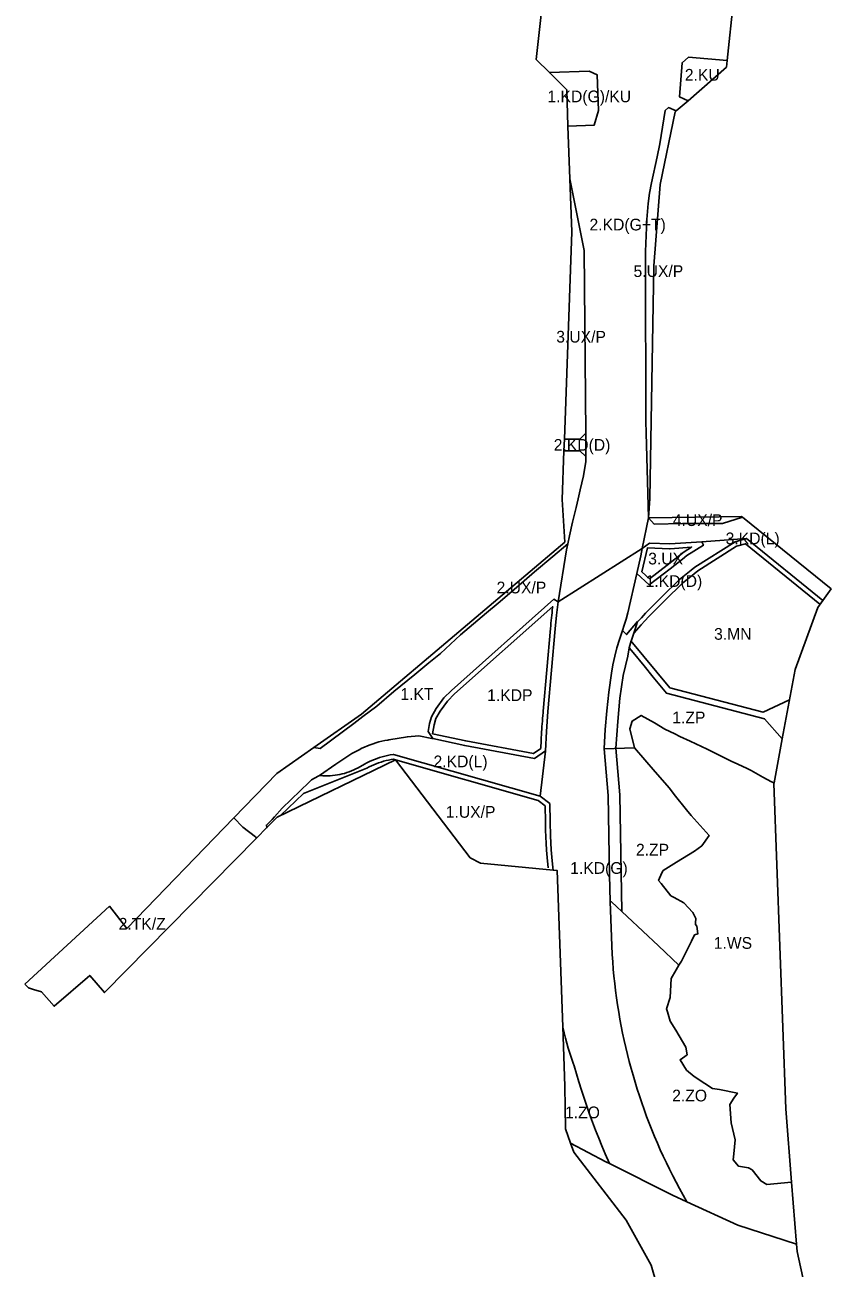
# Model space of a CAD drawing. Extents: x 7426363 to 7427567, y 5543397 to 5546605.
# Drawn here: x 7426639 to 7427327, y 5544381 to 5545441 of the extents above; entities that cross this region are included whole.
import ezdxf

# ---------------------------------------------------------------- set-up
doc = ezdxf.new("R2010")
doc.units = 0
for name, color, linetype in [('linie_rozgraniczajace', 7, 'Continuous'), ('linie_zabudowy_nieprzekraczalne', 7, 'Continuous'), ('oznaczenia_przeznaczen', 7, 'Continuous')]:
    doc.layers.add(name, color=color, linetype=linetype)

msp = doc.modelspace()

# ---------------------------------------------------------------- linework, layer by layer
at = {"layer": 'linie_rozgraniczajace'}
for points in [[(7427243.48, 5545461.46), (7427238, 5545410.26), (7427205.12, 5545413.11), (7427199.67, 5545408.45), (7427197.6, 5545379.31), (7427204.72, 5545376.04), (7427194.76, 5545367.3), (7427188.07, 5545370.22), (7427185.38, 5545367.62), (7427180.65, 5545339.35), (7427178.47, 5545328.2), (7427173.56, 5545306.18), (7427171.87, 5545297.31), (7427170.77, 5545288.36), (7427169.69, 5545274.8), (7427168.92, 5545261.23), (7427168.48, 5545247.63), (7427168.35, 5545234.03), (7427168.7, 5545106.16), (7427168.74, 5545102.69), (7427169.19, 5545093.12), (7427171, 5545020.58), (7427165.78, 5544994.33), (7427093.93, 5544948.99), (7427101.15, 5544993.39), (7427102.23, 5544998.52), (7427103.62, 5545005.17), (7427106.32, 5545016.91), (7427109.3, 5545029.28), (7427111.11, 5545036.83), (7427112.72, 5545044.43), (7427115.53, 5545056.38), (7427117.72, 5545068.46), (7427117.69, 5545072.74), (7427117.54, 5545092.74), (7427116.34, 5545248.29), (7427103.98, 5545309.55), (7427102.39, 5545354.39), (7427124.63, 5545355.18), (7427128.44, 5545367.58), (7427127.37, 5545397.96), (7427120.55, 5545401.26), (7427086.52, 5545400.06), (7427075.42, 5545411.1), (7427081.49, 5545467.8)], [(7427187.34, 5544335.36), (7427173.29, 5544383.64), (7427151.87, 5544421.91), (7427107.4, 5544479.92), (7427104.66, 5544487.48), (7427134.56, 5544471.82), (7427137.7, 5544470.25), (7427191.5, 5544443.31), (7427203.72, 5544437.69), (7427247.33, 5544417.64), (7427297.26, 5544401.56), (7427297.75, 5544395.41), (7427304.02, 5544366.49)]]:
    msp.add_lwpolyline(points, dxfattribs=at)
for points in [[(7427197.6, 5545379.31), (7427199.67, 5545408.45), (7427205.12, 5545413.11), (7427238, 5545410.26), (7427237.41, 5545404.75), (7427204.72, 5545376.04)], [(7427086.52, 5545400.06), (7427120.55, 5545401.26), (7427127.37, 5545397.96), (7427128.44, 5545367.58), (7427124.63, 5545355.18), (7427102.39, 5545354.39), (7427101.3, 5545385.36)], [(7427171, 5545020.58), (7427169.19, 5545093.12), (7427168.74, 5545102.69), (7427168.7, 5545106.16), (7427168.35, 5545234.03), (7427168.48, 5545247.63), (7427168.92, 5545261.23), (7427169.69, 5545274.8), (7427170.77, 5545288.36), (7427171.87, 5545297.31), (7427173.56, 5545306.18), (7427178.47, 5545328.2), (7427180.65, 5545339.35), (7427185.38, 5545367.62), (7427188.07, 5545370.22), (7427194.76, 5545367.3), (7427193.87, 5545366.52), (7427181.09, 5545304.56), (7427175.61, 5545235.36), (7427172.18, 5545037)], [(7427099.34, 5545087.55), (7427105.57, 5545264.4), (7427103.98, 5545309.55), (7427116.34, 5545248.29), (7427117.54, 5545092.74), (7427112.57, 5545087.69)], [(7427098.99, 5545077.54), (7427099.34, 5545087.55), (7427112.57, 5545087.69), (7427117.54, 5545092.74), (7427117.69, 5545072.74), (7427112.65, 5545077.69)], [(7426885.89, 5544824.84), (7426926.31, 5544853.27), (7427099.73, 5544999.86), (7427097.53, 5545036.19), (7427098.99, 5545077.54), (7427112.65, 5545077.69), (7427117.69, 5545072.74), (7427117.72, 5545068.46), (7427115.53, 5545056.38), (7427112.72, 5545044.43), (7427111.11, 5545036.83), (7427109.3, 5545029.28), (7427106.32, 5545016.91), (7427103.62, 5545005.17), (7427102.23, 5544998.52), (7427089.62, 5544987.72), (7427074, 5544974.42), (7427058.51, 5544961.08), (7427042.86, 5544947.85), (7427033.05, 5544939.55), (7427010.66, 5544920.74), (7426993.73, 5544905.07), (7426983.86, 5544896.95), (7426971.75, 5544887.07), (7426954.1, 5544872.43), (7426939.37, 5544859.96), (7426927.61, 5544851.14), (7426919.9, 5544845.35), (7426891.32, 5544823.92)], [(7427165.78, 5544994.33), (7427171, 5545020.58), (7427175.92, 5545015.09), (7427199.95, 5545015.84), (7427234.11, 5545015.81), (7427251.04, 5545021.15), (7427326.72, 5544960.01), (7427319.74, 5544950.23), (7427254.49, 5545002.94), (7427216.55, 5545000.22), (7427189.23, 5544998.26), (7427171.98, 5544998.98)], [(7427171, 5545020.58), (7427231.26, 5545021.26), (7427250.39, 5545021.68), (7427251.04, 5545021.15), (7427234.11, 5545015.81), (7427199.95, 5545015.84), (7427175.92, 5545015.09)], [(7427148.86, 5544924.57), (7427150.35, 5544928.96), (7427152, 5544934.25), (7427153.38, 5544939.62), (7427161.07, 5544973.02), (7427171.73, 5544963.47), (7427189.5, 5544977.01), (7427200.07, 5544985.43), (7427203.72, 5544988.33), (7427217.79, 5544997.2), (7427216.55, 5545000.22), (7427254.49, 5545002.94), (7427244.97, 5545000.17), (7427210.67, 5544978.53), (7427207.54, 5544976.04), (7427197.45, 5544968), (7427182.41, 5544953.33), (7427168.49, 5544939.21), (7427164.94, 5544935.46), (7427161.87, 5544932.17), (7427161.78, 5544932.06), (7427152.33, 5544921.06)], [(7427154.49, 5544909.73), (7427155.7, 5544913.61), (7427159.82, 5544925.75), (7427161.78, 5544932.06), (7427161.87, 5544932.17), (7427164.94, 5544935.46), (7427168.49, 5544939.21), (7427182.41, 5544953.33), (7427197.45, 5544968), (7427207.54, 5544976.04), (7427210.67, 5544978.53), (7427244.97, 5545000.17), (7427254.49, 5545002.94), (7427319.74, 5544950.23), (7427315.34, 5544944.07), (7427296.06, 5544891.36), (7427285.04, 5544832.17), (7427269.92, 5544849.34), (7427186.3, 5544871.19), (7427175.1, 5544884.68), (7427167.35, 5544894.41), (7427157.93, 5544905.68)], [(7426817.63, 5544764.76), (7426854.33, 5544802.65), (7426885.89, 5544824.84), (7426891.32, 5544823.92), (7426919.9, 5544845.35), (7426927.61, 5544851.14), (7426939.37, 5544859.96), (7426954.1, 5544872.43), (7426971.75, 5544887.07), (7426983.86, 5544896.95), (7426993.73, 5544905.07), (7427010.66, 5544920.74), (7427033.05, 5544939.55), (7427042.86, 5544947.85), (7427058.51, 5544961.08), (7427074, 5544974.42), (7427089.62, 5544987.72), (7427102.23, 5544998.52), (7427101.15, 5544993.39), (7427093.93, 5544948.99), (7427090.44, 5544951.19), (7427003.05, 5544873.44), (7426996.67, 5544867.02), (7426989.99, 5544858.04), (7426986.09, 5544850.98), (7426984.39, 5544845.15), (7426983.17, 5544838.43), (7426987.14, 5544832.36), (7426986.48, 5544832.5), (7426975.27, 5544834.86), (7426965.57, 5544834.02), (7426949.72, 5544831.33), (7426948.76, 5544831.17), (7426946.23, 5544830.69), (7426943.71, 5544830.14), (7426941.21, 5544829.51), (7426938.73, 5544828.8), (7426936.28, 5544828.01), (7426933.85, 5544827.15), (7426931.45, 5544826.22), (7426929.08, 5544825.21), (7426926.74, 5544824.12), (7426924.44, 5544822.97), (7426922.18, 5544821.74), (7426920.01, 5544820.52), (7426918.32, 5544819.62), (7426904.46, 5544810.54), (7426890.64, 5544801.06), (7426889.5, 5544800.28), (7426883.93, 5544797.26), (7426881.92, 5544795.31), (7426858.89, 5544773.12), (7426852.35, 5544765.87), (7426850.19, 5544763.46), (7426845.38, 5544758.67), (7426845.76, 5544756.54), (7426836.93, 5544747.57), (7426835.95, 5544748.61), (7426825.13, 5544756.91)], [(7427078.7, 5544783.4), (7427083.19, 5544821.57), (7427083.21, 5544821.91), (7427083.99, 5544838.56), (7427085.26, 5544855.53), (7427091.47, 5544925.97), (7427092.6, 5544937.49), (7427093.93, 5544948.99), (7427165.78, 5544994.33), (7427164.56, 5544988.2), (7427161.07, 5544973.02), (7427153.38, 5544939.62), (7427152, 5544934.25), (7427150.35, 5544928.96), (7427148.86, 5544924.57), (7427146.21, 5544916.77), (7427144.07, 5544909.71), (7427142.24, 5544902.56), (7427140.72, 5544895.34), (7427139.52, 5544888.06), (7427137.3, 5544872.11), (7427135.52, 5544856.1), (7427134.19, 5544840.04), (7427133.31, 5544823.96), (7427133.34, 5544823.61), (7427136.53, 5544783.85), (7427137.71, 5544716.09), (7427138.5, 5544693.57), (7427140.1, 5544648.28), (7427140.52, 5544642.12), (7427141.02, 5544635.99), (7427141.59, 5544629.87), (7427142.24, 5544623.75), (7427142.98, 5544617.65), (7427143.79, 5544611.55), (7427144.68, 5544605.47), (7427145.64, 5544599.4), (7427146.69, 5544593.34), (7427147.81, 5544587.3), (7427149.01, 5544581.27), (7427150.29, 5544575.25), (7427151.65, 5544569.26), (7427153.08, 5544563.28), (7427154.59, 5544557.32), (7427156.18, 5544551.38), (7427157.84, 5544545.46), (7427159.58, 5544539.56), (7427161.39, 5544533.69), (7427163.28, 5544527.84), (7427165.25, 5544522.01), (7427167.29, 5544516.21), (7427169.4, 5544510.44), (7427171.59, 5544504.69), (7427173.86, 5544498.98), (7427176.19, 5544493.29), (7427178.6, 5544487.63), (7427181.08, 5544482.01), (7427183.64, 5544476.42), (7427186.26, 5544470.86), (7427188.96, 5544465.33), (7427191.73, 5544459.84), (7427194.57, 5544454.39), (7427197.48, 5544448.97), (7427203.72, 5544437.69), (7427191.5, 5544443.31), (7427137.7, 5544470.25), (7427134.13, 5544478.53), (7427131.33, 5544485.23), (7427128.61, 5544491.96), (7427125.96, 5544498.72), (7427123.39, 5544505.5), (7427120.89, 5544512.32), (7427118.47, 5544519.16), (7427116.12, 5544526.03), (7427113.85, 5544532.92), (7427111.66, 5544539.84), (7427109.54, 5544546.78), (7427107.56, 5544553.57), (7427106.74, 5544555.81), (7427105.28, 5544560.03), (7427103.9, 5544564.29), (7427102.59, 5544568.57), (7427101.36, 5544572.88), (7427100.21, 5544577.2), (7427099.14, 5544581.55), (7427098.15, 5544585.92), (7427097.99, 5544586.69), (7427093.22, 5544719.96), (7427089.67, 5544720.3), (7427089.49, 5544722.5), (7427088.73, 5544731.31), (7427088.13, 5544737.66), (7427087.49, 5544749.61), (7427087.18, 5544761.57), (7427086.86, 5544777.05)], [(7427161.07, 5544973.02), (7427164.56, 5544988.2), (7427165.78, 5544994.33), (7427171.98, 5544998.98), (7427189.23, 5544998.26), (7427216.55, 5545000.22), (7427217.79, 5544997.2), (7427203.72, 5544988.33), (7427200.07, 5544985.43), (7427189.5, 5544977.01), (7427171.73, 5544963.47)], [(7426983.17, 5544838.43), (7426984.39, 5544845.15), (7426986.09, 5544850.98), (7426989.99, 5544858.04), (7426996.67, 5544867.02), (7427003.05, 5544873.44), (7427090.44, 5544951.19), (7427093.93, 5544948.99), (7427092.6, 5544937.49), (7427091.47, 5544925.97), (7427085.26, 5544855.53), (7427083.99, 5544838.56), (7427083.21, 5544821.91), (7427073.92, 5544815.36), (7427014.43, 5544826.46), (7426987.14, 5544832.36)], [(7427133.31, 5544823.96), (7427134.19, 5544840.04), (7427135.52, 5544856.1), (7427137.3, 5544872.11), (7427139.52, 5544888.06), (7427140.72, 5544895.34), (7427142.24, 5544902.56), (7427144.07, 5544909.71), (7427146.21, 5544916.77), (7427148.86, 5544924.57), (7427152.33, 5544921.06), (7427161.78, 5544932.06), (7427159.82, 5544925.75), (7427155.7, 5544913.61), (7427154.49, 5544909.73), (7427157.93, 5544905.68), (7427167.35, 5544894.41), (7427175.1, 5544884.68), (7427186.3, 5544871.19), (7427269.92, 5544849.34), (7427285.04, 5544832.17), (7427278.07, 5544794.72), (7427275.83, 5544795.49), (7427268.54, 5544799.6), (7427258.57, 5544805.28), (7427255.03, 5544806.94), (7427247.14, 5544810.73), (7427241.55, 5544813.2), (7427230.79, 5544818.43), (7427220.98, 5544823.3), (7427206.64, 5544830.15), (7427197.87, 5544834.32), (7427193.44, 5544836.37), (7427185.05, 5544840.39), (7427176.02, 5544845.81), (7427164.89, 5544852.22), (7427157.25, 5544847.35), (7427155.01, 5544840.84), (7427159.09, 5544824.66), (7427133.34, 5544823.61)], [(7427155.01, 5544840.84), (7427157.25, 5544847.35), (7427164.89, 5544852.22), (7427176.02, 5544845.81), (7427185.05, 5544840.39), (7427193.44, 5544836.37), (7427197.87, 5544834.32), (7427206.64, 5544830.15), (7427220.98, 5544823.3), (7427230.79, 5544818.43), (7427241.55, 5544813.2), (7427247.14, 5544810.73), (7427255.03, 5544806.94), (7427258.57, 5544805.28), (7427268.54, 5544799.6), (7427275.83, 5544795.49), (7427278.07, 5544794.72), (7427277.99, 5544794.28), (7427288.06, 5544516.77), (7427293.05, 5544454.25), (7427271.99, 5544452.53), (7427266.66, 5544455.5), (7427259.36, 5544464.79), (7427256.31, 5544466.46), (7427247.74, 5544468.12), (7427243.23, 5544473.37), (7427243.82, 5544478.4), (7427244.79, 5544490.58), (7427241.37, 5544504.99), (7427240.34, 5544520.63), (7427243.79, 5544526.04), (7427246.85, 5544530.33), (7427231.48, 5544533.28), (7427225.67, 5544534.28), (7427219.09, 5544538.61), (7427209.91, 5544544.41), (7427203.52, 5544549.89), (7427198.02, 5544558.71), (7427204.02, 5544562.92), (7427202.76, 5544569.38), (7427194.4, 5544583.79), (7427189.51, 5544591.59), (7427187.29, 5544599.61), (7427186.39, 5544602.08), (7427189.59, 5544611.88), (7427190.34, 5544627.96), (7427194.65, 5544635.31), (7427197, 5544639.19), (7427199.21, 5544642.83), (7427201.65, 5544647.7), (7427207.57, 5544659.68), (7427210.35, 5544665.13), (7427213.06, 5544665.88), (7427212.35, 5544672.59), (7427211.23, 5544673.94), (7427211.07, 5544675.41), (7427211.48, 5544679.19), (7427208.87, 5544684.32), (7427201.17, 5544692.32), (7427192.98, 5544696.92), (7427190.19, 5544698.35), (7427181.95, 5544708.85), (7427179.67, 5544711.56), (7427182.42, 5544717.95), (7427183.51, 5544719.86), (7427194.96, 5544727.03), (7427210.16, 5544736.42), (7427216.49, 5544740.97), (7427222.66, 5544749.84), (7427207.36, 5544766.8), (7427203.56, 5544771.65), (7427193.05, 5544784.84), (7427188.85, 5544790.23), (7427176.87, 5544804.11), (7427159.09, 5544824.66)], [(7426890.64, 5544801.06), (7426904.46, 5544810.54), (7426918.32, 5544819.62), (7426920.01, 5544820.52), (7426922.18, 5544821.74), (7426924.44, 5544822.97), (7426926.74, 5544824.12), (7426929.08, 5544825.21), (7426931.45, 5544826.22), (7426933.85, 5544827.15), (7426936.28, 5544828.01), (7426938.73, 5544828.8), (7426941.21, 5544829.51), (7426943.71, 5544830.14), (7426946.23, 5544830.69), (7426948.76, 5544831.17), (7426949.72, 5544831.33), (7426965.57, 5544834.02), (7426975.27, 5544834.86), (7426986.48, 5544832.5), (7426987.14, 5544832.36), (7427014.43, 5544826.46), (7427073.92, 5544815.36), (7427083.21, 5544821.91), (7427083.19, 5544821.57), (7427078.7, 5544783.4), (7426953.71, 5544818.87), (7426953.29, 5544818.82), (7426950.98, 5544818.46), (7426948.68, 5544818.03), (7426946.39, 5544817.51), (7426944.13, 5544816.92), (7426941.89, 5544816.25), (7426939.67, 5544815.51), (7426937.47, 5544814.69), (7426935.31, 5544813.8), (7426933.18, 5544812.83), (7426931.08, 5544811.79), (7426929.02, 5544810.68), (7426923.51, 5544807.58), (7426921.68, 5544806.6), (7426919.81, 5544805.69), (7426917.91, 5544804.85), (7426915.97, 5544804.08), (7426914.01, 5544803.39), (7426912.03, 5544802.78), (7426910.02, 5544802.24), (7426907.99, 5544801.78), (7426905.95, 5544801.4), (7426903.89, 5544801.1), (7426901.83, 5544800.88), (7426899.75, 5544800.73), (7426897.68, 5544800.67), (7426895.6, 5544800.69), (7426893.52, 5544800.78), (7426891.45, 5544800.96)], [(7427138.5, 5544693.57), (7427137.71, 5544716.09), (7427136.53, 5544783.85), (7427133.34, 5544823.61), (7427159.09, 5544824.66), (7427176.87, 5544804.11), (7427188.85, 5544790.23), (7427193.05, 5544784.84), (7427203.56, 5544771.65), (7427207.36, 5544766.8), (7427222.66, 5544749.84), (7427216.49, 5544740.97), (7427210.16, 5544736.42), (7427194.96, 5544727.03), (7427183.51, 5544719.86), (7427182.42, 5544717.95), (7427179.67, 5544711.56), (7427181.95, 5544708.85), (7427190.19, 5544698.35), (7427192.98, 5544696.92), (7427201.17, 5544692.32), (7427208.87, 5544684.32), (7427211.48, 5544679.19), (7427211.07, 5544675.41), (7427211.23, 5544673.94), (7427212.35, 5544672.59), (7427213.06, 5544665.88), (7427210.35, 5544665.13), (7427207.57, 5544659.68), (7427201.65, 5544647.7), (7427199.21, 5544642.83), (7427197, 5544639.19), (7427179.47, 5544655.68), (7427139.57, 5544693.16)], [(7426845.38, 5544758.67), (7426850.19, 5544763.46), (7426852.35, 5544765.87), (7426858.89, 5544773.12), (7426881.92, 5544795.31), (7426883.93, 5544797.26), (7426889.5, 5544800.28), (7426890.64, 5544801.06), (7426891.45, 5544800.96), (7426893.52, 5544800.78), (7426895.6, 5544800.69), (7426897.68, 5544800.67), (7426899.75, 5544800.73), (7426901.83, 5544800.88), (7426903.89, 5544801.1), (7426905.95, 5544801.4), (7426907.99, 5544801.78), (7426910.02, 5544802.24), (7426912.03, 5544802.78), (7426914.01, 5544803.39), (7426915.97, 5544804.08), (7426917.91, 5544804.85), (7426919.81, 5544805.69), (7426921.68, 5544806.6), (7426923.51, 5544807.58), (7426929.02, 5544810.68), (7426931.08, 5544811.79), (7426933.18, 5544812.83), (7426935.31, 5544813.8), (7426937.47, 5544814.69), (7426939.67, 5544815.51), (7426941.89, 5544816.25), (7426944.13, 5544816.92), (7426946.39, 5544817.51), (7426948.68, 5544818.03), (7426950.98, 5544818.46), (7426953.29, 5544818.82), (7426953.71, 5544818.87), (7427078.7, 5544783.4), (7427086.86, 5544777.05), (7427087.18, 5544761.57), (7427087.49, 5544749.61), (7427088.13, 5544737.66), (7427088.73, 5544731.31), (7427089.49, 5544722.5), (7427089.67, 5544720.3), (7427027.96, 5544726.16), (7427019.17, 5544730.66), (7426955.54, 5544814.23), (7426854.44, 5544765.36), (7426845.76, 5544756.54)], [(7426639.48, 5544623.2), (7426711.57, 5544689.57), (7426726.52, 5544670.7), (7426817.63, 5544764.76), (7426825.13, 5544756.91), (7426835.95, 5544748.61), (7426836.93, 5544747.57), (7426707.34, 5544615.92), (7426694.75, 5544630.56), (7426664.36, 5544604.33), (7426653.75, 5544616.45), (7426646.88, 5544618.7), (7426642.68, 5544620.08)], [(7427140.1, 5544648.28), (7427138.5, 5544693.57), (7427139.57, 5544693.16), (7427179.47, 5544655.68), (7427197, 5544639.19), (7427194.65, 5544635.31), (7427190.34, 5544627.96), (7427189.59, 5544611.88), (7427186.39, 5544602.08), (7427187.29, 5544599.61), (7427189.51, 5544591.59), (7427194.4, 5544583.79), (7427202.76, 5544569.38), (7427204.02, 5544562.92), (7427198.02, 5544558.71), (7427203.52, 5544549.89), (7427209.91, 5544544.41), (7427219.09, 5544538.61), (7427225.67, 5544534.28), (7427231.48, 5544533.28), (7427246.85, 5544530.33), (7427243.79, 5544526.04), (7427240.34, 5544520.63), (7427241.37, 5544504.99), (7427244.79, 5544490.58), (7427243.82, 5544478.4), (7427243.23, 5544473.37), (7427247.74, 5544468.12), (7427256.31, 5544466.46), (7427259.36, 5544464.79), (7427266.66, 5544455.5), (7427271.99, 5544452.53), (7427293.05, 5544454.25), (7427297.26, 5544401.56), (7427247.33, 5544417.64), (7427203.72, 5544437.69), (7427197.48, 5544448.97), (7427194.57, 5544454.39), (7427191.73, 5544459.84), (7427188.96, 5544465.33), (7427186.26, 5544470.86), (7427183.64, 5544476.42), (7427181.08, 5544482.01), (7427178.6, 5544487.63), (7427176.19, 5544493.29), (7427173.86, 5544498.98), (7427171.59, 5544504.69), (7427169.4, 5544510.44), (7427167.29, 5544516.21), (7427165.25, 5544522.01), (7427163.28, 5544527.84), (7427161.39, 5544533.69), (7427159.58, 5544539.56), (7427157.84, 5544545.46), (7427156.18, 5544551.38), (7427154.59, 5544557.32), (7427153.08, 5544563.28), (7427151.65, 5544569.26), (7427150.29, 5544575.25), (7427149.01, 5544581.27), (7427147.81, 5544587.3), (7427146.69, 5544593.34), (7427145.64, 5544599.4), (7427144.68, 5544605.47), (7427143.79, 5544611.55), (7427142.98, 5544617.65), (7427142.24, 5544623.75), (7427141.59, 5544629.87), (7427141.02, 5544635.99), (7427140.52, 5544642.12)], [(7427100.21, 5544499.82), (7427099.79, 5544536.27), (7427097.99, 5544586.69), (7427098.15, 5544585.92), (7427099.14, 5544581.55), (7427100.21, 5544577.2), (7427101.36, 5544572.88), (7427102.59, 5544568.57), (7427103.9, 5544564.29), (7427105.28, 5544560.03), (7427106.74, 5544555.81), (7427107.56, 5544553.57), (7427109.54, 5544546.78), (7427111.66, 5544539.84), (7427113.85, 5544532.92), (7427116.12, 5544526.03), (7427118.47, 5544519.16), (7427120.89, 5544512.32), (7427123.39, 5544505.5), (7427125.96, 5544498.72), (7427128.61, 5544491.96), (7427131.33, 5544485.23), (7427134.13, 5544478.53), (7427137.7, 5544470.25), (7427134.56, 5544471.82), (7427104.66, 5544487.48)]]:
    msp.add_lwpolyline(points, close=True, dxfattribs=at)
at = {"layer": 'linie_zabudowy_nieprzekraczalne'}
for points in [[(7427317.22, 5544947.11), (7427253.6, 5544998.52), (7427246.09, 5544996.33), (7427212.99, 5544975.26), (7427210.03, 5544972.91), (7427200.1, 5544965), (7427185.23, 5544950.49), (7427171.37, 5544936.43), (7427167.86, 5544932.72), (7427164.85, 5544929.5), (7427158.96, 5544922.64)], [(7427165.49, 5544974.42), (7427171.94, 5544968.65), (7427187.04, 5544980.17), (7427197.58, 5544988.56), (7427201.4, 5544991.59), (7427207.71, 5544995.58), (7427189.52, 5544994.27), (7427189.07, 5544994.26), (7427170.24, 5544995.05), (7427165.49, 5544974.42)], [(7426986.88, 5544836.51), (7427015.22, 5544830.38), (7427072.99, 5544819.61), (7427079.27, 5544824.04), (7427079.37, 5544826.37), (7427079.47, 5544828.7), (7427079.59, 5544831.03), (7427079.7, 5544833.36), (7427079.83, 5544835.69), (7427079.97, 5544838.02), (7427080.11, 5544840.35), (7427080.26, 5544842.68), (7427080.42, 5544845.01), (7427080.59, 5544847.34), (7427080.77, 5544849.66), (7427080.95, 5544851.99), (7427081.14, 5544854.32), (7427081.27, 5544855.88), (7427087.49, 5544926.32), (7427087.69, 5544928.55), (7427087.9, 5544930.78), (7427088.11, 5544933.01), (7427088.34, 5544935.24), (7427088.57, 5544937.47), (7427088.81, 5544939.7), (7427089.06, 5544941.93), (7427089.32, 5544944.15), (7427089.41, 5544944.92), (7427005.8, 5544870.54), (7426999.71, 5544864.4), (7426993.36, 5544855.87), (7426989.8, 5544849.44), (7426988.29, 5544844.23), (7426986.88, 5544836.51)], [(7427154.49, 5544909.73), (7427153.33, 5544902.74), (7427149.35, 5544886.13), (7427146.75, 5544866.76), (7427144.77, 5544846.93), (7427143.31, 5544824.33), (7427146.53, 5544784.34), (7427148.25, 5544685.01)], [(7427155.96, 5544915.84), (7427189.12, 5544875.62)], [(7427189.12, 5544875.62), (7427268.71, 5544854.83), (7427291.1, 5544865.38)], [(7427085.51, 5544722.16), (7427084.74, 5544730.95), (7427084.14, 5544737.28), (7427084.14, 5544737.39), (7427084.01, 5544739.28), (7427083.9, 5544741.17), (7427083.8, 5544743.06), (7427083.7, 5544744.95), (7427083.61, 5544746.84), (7427083.53, 5544748.73), (7427083.45, 5544750.62), (7427083.39, 5544752.52), (7427083.33, 5544754.41), (7427083.28, 5544756.3), (7427083.24, 5544758.19), (7427083.2, 5544760.08), (7427083.18, 5544761.52), (7427083.18, 5544761.49), (7427082.9, 5544775.06), (7427076.86, 5544779.76), (7426953.44, 5544814.79), (7426951.65, 5544814.52), (7426949.49, 5544814.11), (7426947.34, 5544813.63), (7426945.2, 5544813.07), (7426943.09, 5544812.44), (7426941, 5544811.74), (7426938.94, 5544810.97), (7426936.9, 5544810.13), (7426934.89, 5544809.21), (7426932.92, 5544808.24), (7426930.92, 5544807.16), (7426877.02, 5544785.58), (7426857.27, 5544766.73)]]:
    msp.add_lwpolyline(points, dxfattribs=at)

# ---------------------------------------------------------------- texts
at = {"layer": 'oznaczenia_przeznaczen'}
for s, p in [('2.KU', (7427202.02, 5545393.11)), ('1.KD(G)/KU', (7427084.91, 5545374.69)), ('2.KD(G+T)', (7427120.76, 5545265.47)), ('5.UX/P', (7427158.28, 5545225.81)), ('3.UX/P', (7427092.41, 5545169.9)), ('2.KD(D)', (7427090.26, 5545077.72)), ('4.UX/P', (7427191.77, 5545013.58)), ('3.KD(L)', (7427236.78, 5544998.02)), ('3.UX', (7427170.79, 5544980.82)), ('1.KD(D)', (7427168.56, 5544961.66)), ('2.UX/P', (7427041.56, 5544956.16)), ('3.MN', (7427226.95, 5544916.63)), ('1.KT', (7426959.57, 5544865.4)), ('1.KDP', (7427033.55, 5544864.4)), ('1.ZP', (7427191.31, 5544845.42)), ('2.KD(L)', (7426987.8, 5544807.95)), ('1.UX/P', (7426998.24, 5544764.94)), ('2.ZP', (7427160.35, 5544732.73)), ('1.KD(G)', (7427104.3, 5544717.15)), ('2.TK/Z', (7426719.43, 5544669.6)), ('1.WS', (7427226.65, 5544653.24)), ('2.ZO', (7427191.23, 5544523.2)), ('1.ZO', (7427099.88, 5544508.83))]:
    msp.add_text(s, height=10, dxfattribs=at).set_placement(p)

doc.saveas('drawing.dxf')
